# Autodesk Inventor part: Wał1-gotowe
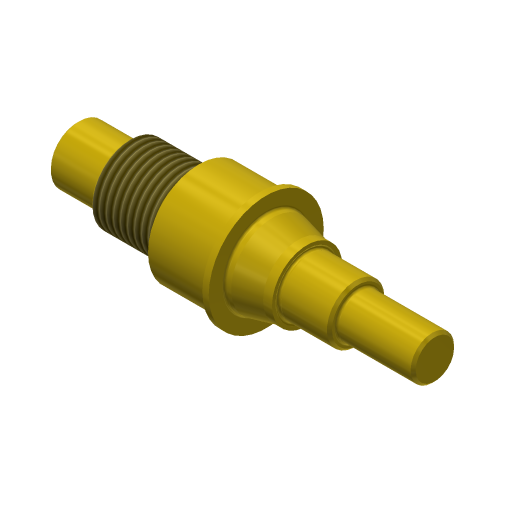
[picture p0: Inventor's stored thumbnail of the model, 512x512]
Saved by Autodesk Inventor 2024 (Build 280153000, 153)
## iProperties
Company: ATC
CustomPartVersion: 1
Created: 2023-03
Part Number: Wał1-gotowe
Material: Stal kuta
Document SubType Name: Modeling
Designer: Andrzej Jaskulski
Density: 1 g/cm^3
Stock Number: Wał1-gotowe
Appearance: Lśniąca — złota
Checked By: A.J.
Engr Approved By: Andrzej Jaskulski
Mfg Approved By: Andrzej Jaskulski
Authority: A.J.
Title: A.J.: Kurs R2024-MEP
Author: Andrzej Jaskulski
Revision Number: 1/24
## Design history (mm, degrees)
sketch "Szkic główny"
  geometry: L1 (0, 0)-(280, 0) reference; L2 (0, 0)-(0, 22.5); L3 (0, 22.5)-(40, 22.5); L4 (40, 22.5)-(40, 30); L5 (90, 30)-(90, 27.5); L6 (40, 30)-(90, 30); L7 (90, 27.5)-(95, 27.5); L8 (95, 27.5)-(95, 40); L9 (95, 40)-(143, 40); L10 (143, 40)-(143, 45); L11 (148, 45)-(148, 32.5); L12 (143, 45)-(148, 45); L13 (148, 32.5)-(153, 32.5); L14 (153, 32.5)-(173, 27.5); L15 (180, 27.5)-(180, 22.5); L16 (173, 27.5)-(180, 27.5); L17 (220, 22.5)-(220, 17); L18 (180, 22.5)-(220, 22.5); L19 (280, 17)-(280, 0); L20 (220, 17)-(280, 17)
  constraints: 40 end point, 11 horizontal, 9 vertical
revolve "Obrót1" sketch "Szkic główny" stored, may be unused: angle "d6" = 0 deg
chamfer "Faza12" distance "d56" = 2; stored, may be unused: second distance "d57" = 0.125, angle "d58" = 45 deg
fillet "Zaokrąglenie7" dims "d59" = 2
chamfer "Faza13" distance "d60" = 2; stored, may be unused: second distance "d61" = 0.125, angle "d62" = 45 deg
feature "Gwint3" dims "d63" = 50, "d64" = 0
chamfer "Faza14" distance "d65" = 2; stored, may be unused: second distance "d66" = 2, angle "d67" = 45 deg
fillet "Zaokrąglenie8" dims "d68" = 0.5
fillet "Zaokrąglenie9" dims "d69" = 0.5
chamfer "Faza15" distance "d70" = 0.5; stored, may be unused: second distance "d71" = 0.125, angle "d72" = 45 deg
node "Podcięcie4"
fillet "Zaokrąglenie10" dims "d73" = 2
node "Podcięcie5"
chamfer "Faza16" distance "d74" = 2; stored, may be unused: second distance "d75" = 0.125, angle "d76" = 45 deg
fillet "Zaokrąglenie11" dims "d77" = 2
chamfer "Faza17" distance "d78" = 2; stored, may be unused: second distance "d79" = 0.125, angle "d80" = 45 deg
node "Bryła1"
node "Korpusy bryłowe"
node "Korpusy powierzchniowe"
feature "iFeature1:3"
feature "iFeature1:4"
other parameters: "d0" = 0, "d1" = 0, "d2" = 0
